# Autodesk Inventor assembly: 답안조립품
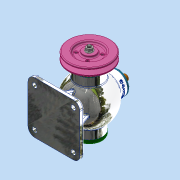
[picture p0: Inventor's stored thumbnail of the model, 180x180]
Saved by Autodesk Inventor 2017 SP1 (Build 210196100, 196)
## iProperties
Part Number: 답안조립품
Material: 일반
Document SubType Name: Assembly
Designer: MRC
Author: MRC
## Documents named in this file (16)
- C:\Users\MRC\Desktop\720811V1012\답안조립품.iam
- C:\Users\MRC\Desktop\720811V1012\본체.ipt
- C:\Users\MRC\Desktop\720811V1012\V-벨트풀리.ipt
- C:\Users\MRC\Desktop\720811V1012\너트 M8.ipt
- C:\Users\MRC\Desktop\720811V1012\뒤커버.ipt
- C:\Users\MRC\Desktop\720811V1012\베어링- 6202.ipt
- KS B 2023 - 6202 - 15 x 35 x 11 - 7.8.ipt
- C:\Users\MRC\Desktop\720811V1012\볼트 M4 x 12.ipt
- C:\Users\MRC\Desktop\720811V1012\볼트 M4 x 16.ipt
- C:\Users\MRC\Desktop\720811V1012\상부커버.ipt
- C:\Users\MRC\Desktop\720811V1012\슬라이드.ipt
- C:\Users\MRC\Desktop\720811V1012\앞커버.ipt
- C:\Users\MRC\Desktop\720811V1012\오일실 15 30 7.ipt
- C:\Users\MRC\Desktop\720811V1012\칼라.ipt
- C:\Users\MRC\Desktop\720811V1012\키 4 x 4 x 12.ipt
- C:\Users\MRC\Desktop\720811V1012\편심축.ipt
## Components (15 placed, 4 different names)
1. V-벨트풀리:1
2. KS B 2023 - 6202 - 15 x 35 x 11 - 7.8:1
3. KS B 2023 - 6202 - 15 x 35 x 11 - 7.8:2
4. ISO 4762 M4 x 16:1
5. ISO 4762 M4 x 16:3
6. ISO 4762 M4 x 16:4
7. ISO 4762 M4 x 16:5
8. ISO 4762 M4 x 16:2
9. ISO 4762 M4 x 16:6
10. ISO 4762 M4 x 16:7
11. ISO 4762 M4 x 16:8
12. KS B 1021 - 에 따름 ISO 1207 - 미터 A  M 4 x 12:1
13. KS B 1021 - 에 따름 ISO 1207 - 미터 A  M 4 x 12:2
14. KS B 1021 - 에 따름 ISO 1207 - 미터 A  M 4 x 12:3
15. KS B 1021 - 에 따름 ISO 1207 - 미터 A  M 4 x 12:4
